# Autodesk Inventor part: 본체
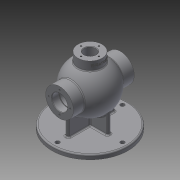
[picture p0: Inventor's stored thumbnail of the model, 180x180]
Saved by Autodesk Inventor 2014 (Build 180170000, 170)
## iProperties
Created: 2020-08
Part Number: 본체
Material: Generic
Document SubType Name: Modeling
Designer: kh
Density: 1 g/cm^3
Appearance: Default
Author: kh
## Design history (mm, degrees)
sketch "Sketch1"
  geometry: C1 r 85 at (0, 0); 1 further point
  constraints: 1 centre point, 1 coincident
  dimensions: "d0" = 170 diameter of C1
extrude "Extrusion1" new body sketch "Sketch1" distance "d1" = 10; taper "d2" = 0 deg
sketch "Sketch2"
  geometry: L1 (0, 0)-(0, 85); L2 (0, 138)-(0, 32); L3 (0, 32)-(0, 0); A1 r 53 centre (0, 85) between (0, 138) and (0, 32)
  constraints: 6 end point, 2 collinear, 2 point on circle, 1 centre point, 1 coincident, 1 midpoint, 1 vertical
  dimensions: "d3" = 85 distance of L1.end L1.start; "d4" = 53 radius of A1
revolve "Revolution1" sketch "Sketch2" stored, may be unused: angle "d5" = 90 deg
sketch "Sketch3"
  geometry: C1 r 53 at (0, 85) reference; C2 r 31 at (0, 85); 1 further point
  constraints: 1 centre point, 1 coincident
  dimensions: "d6" = 62 diameter of C2
extrude "Extrusion2" join sketch "Sketch3" stored distance "d7" = 136; taper "d8" = 0 deg
workplane "Work Plane1"
sketch "Sketch4"
  geometry: C1 r 27 at (0, 0); 1 further point
  constraints: 1 centre point, 1 coincident
  dimensions: "d10" = 54 diameter of C1
extrude "Extrusion3" join sketch "Sketch4" stored distance "d11" = 136; taper "d12" = 0 deg
sketch "Sketch5"
  geometry: L1 (-43, -4)-(43, -4); L2 (43, -4)-(43, 4); L3 (43, 4)-(-43, 4); L4 (-43, 4)-(-43, -4); L5 (-43, -4)-(43, 4); L6 (43, -4)-(-43, 4); L7 (-4, -52)-(4, -52); L8 (4, -52)-(4, 52); L9 (4, 52)-(-4, 52); L10 (-4, 52)-(-4, -52); L11 (-4, -52)-(4, 52); L12 (4, -52)-(-4, 52); 1 further point
  constraints: 24 end point, 4 midpoint, 4 parallel, 2 horizontal, 2 perpendicular
  dimensions: "d13" = 86 distance of L3.end L2.end; "d14" = 8 distance of L2.end L1.end; "d15" = 8 distance of L9.end L8.end; "d16" = 104 distance of L8.end L7.end
extrude "Extrusion4" join sketch "Sketch5" stored distance "d17" = 136; taper "d18" = 0 deg
sketch "Sketch6" dims "d19" = 145
  geometry: C1 r 4.5 at (0, 72.5); 2 further points
  constraints: 2 vertical alignment, 1 centre point, 1 coincident, 2 other
  dimensions: "d20" = 9 diameter of C1
extrude "Extrusion5" cut sketch "Sketch6" stored distance "d21" = 136; taper "d22" = 0 deg
pattern_circular "Circular Pattern1" dims angle "d24" = 360 deg
sketch "Sketch7"
  geometry: C1 r 31 at (0, 0) reference; C2 r 17.5 at (0, 0); 1 further point
  constraints: 1 centre point, 1 coincident
  dimensions: "d26" = 35 diameter of C2
extrude "Extrusion6" cut sketch "Sketch7" stored distance "d27" = 136; taper "d28" = 0 deg
sketch "Sketch8"
  geometry: L1 (0, 0)-(0, 138); L2 (-13, 125.988)-(-13, 150); L3 (-27, 130.607)-(27, 130.607) reference; L4 (-27, 150)-(27, 150) reference; L5 (-13, 150)-(0, 150); L6 (0, 150)-(0, 42); A1 r 53 centre (0, 85) between (42.988, 116) and (-42.988, 116) reference; A2 r 43 centre (0, 85) between (-13, 125.988) and (0, 42)
  constraints: 8 end point, 3 point on circle, 1 centre point, 1 coincident, 1 collinear, 1 midpoint, 1 parallel, 1 point on line
  dimensions: "d29" = 43 radius of A2; "d30" = 26 diameter of L2 L1
revolve "Revolution2" sketch "Sketch8" stored, may be unused: angle "d31" = 90 deg
sketch "Sketch9"
  geometry: L1 (-68, 67.5)-(-68, 102.5) reference; L2 (-39.278, 67.5)-(-39.278, 102.5) reference; L3 (-68, 85)-(-39.278, 85); L4 (-52, 85)-(-50.25, 85); L5 (-50.25, 85)-(-50.25, 66.5); L6 (-50.25, 66.5)-(-52, 66.5); L7 (-52, 66.5)-(-52, 85); 1 further point
  constraints: 10 end point, 2 midpoint, 2 parallel, 1 horizontal, 1 perpendicular, 1 point on line
  dimensions: "d32" = 1.75 distance of L5.end L6.end; "d33" = 16 distance between parallel lines of L1 L7; "d34" = 37 diameter of L6 L3
revolve "Revolution3" sketch "Sketch9" stored, may be unused: angle "d35" = 90 deg
sketch "Sketch10"
  geometry: L1 (0, 0)-(0, 20); 1 further point
  constraints: 2 end point, 1 coincident, 1 vertical
  dimensions: "d36" = 20 distance of L1.start L1.end
hole "Hole1" sketch "Sketch10" at (0, 20) diameter "d37" = 3.242; stored, may be unused: countersink angle "d41" = 90 deg, drill point angle "d43" = 118 deg; dims "d38" = 12, "d39" = 4, "d40" = 2, "d42" = 15
pattern_circular "Circular Pattern2" dims angle "d45" = 360 deg
sketch "Sketch11"
  geometry: L1 (0, 0)-(0, 24); C1 r 31 at (0, 0) reference; 2 further points
  constraints: 2 end point, 1 coincident, 1 vertical
  dimensions: "d47" = 24 distance of L1.start L1.end
hole "Hole2" sketch "Sketch11" at (0, 24) diameter "d48" = 3.242; stored, may be unused: countersink angle "d52" = 90 deg, drill point angle "d54" = 118 deg; dims "d49" = 12, "d50" = 4, "d51" = 2, "d53" = 15
pattern_circular "Circular Pattern3" dims angle "d56" = 360 deg
mirror "Mirror1"
workplane "Work Plane2"
sketch "Sketch12"
  geometry: L1 (-20.016, -2.862)-(20.016, -2.862); L2 (20.016, -2.862)-(20.016, -15.138); L3 (20.016, -15.138)-(-20.016, -15.138); L4 (-20.016, -15.138)-(-20.016, -2.862); L5 (-20.016, -15.138)-(20.016, -2.862); L6 (-27, 0)-(27, 0) reference; 2 further points
  constraints: 2 end point, 1 midpoint, 2 other
  dimensions: "d58" = 9 distance from line of point (0, -9) L6; "d59" = 27 horizontal distance of point (0, -9) L6.start
emboss "Emboss1" sketch "Sketch12" dims "d60" = 0.5, "d61" = 0
fillet "Fillet1" dims "d62" = 3
fillet "Fillet2" dims "d63" = 3
fillet "Fillet3" dims "d64" = 3
fillet "Fillet4" dims "d65" = 3
chamfer "Chamfer1" distance "d66" = 1; stored, may be unused: second distance "d67" = 2, angle "d68" = 45 deg
body "Solid1"
node "Projected Loop1"
node "Projected Loop2"
node "Projected Loop3"
